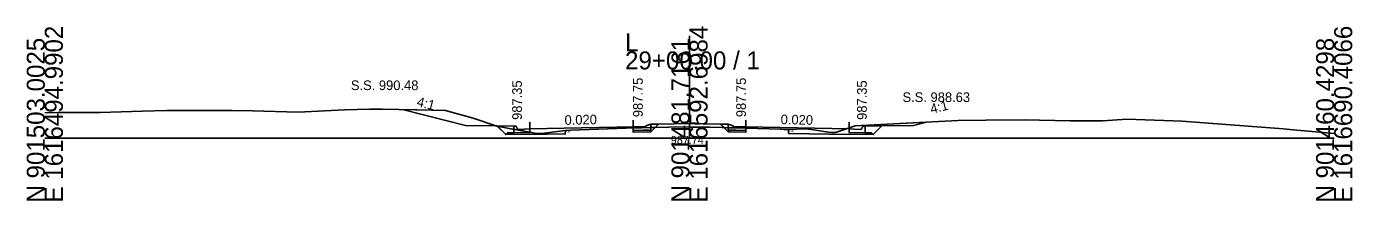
# Model space of a CAD drawing. Extents: x 1009 to 7438, y -1586 to 7964.
# Drawn here: x 2032.1 to 2237.7, y 6914 to 6941.1 of the extents above; entities that cross this region are included whole.
import ezdxf

# ---------------------------------------------------------------- set-up
doc = ezdxf.new("R2010")
doc.units = 0
for name, color, linetype in [('Default', 7, 'Continuous'), ('Exist Cross Section Cell', 7, 'Continuous'), ('Exist XS Center Line Elevation Label', 7, 'Continuous'), ('Exist XS Ground Line', 7, 'Continuous'), ('Prop XS Dump Level', 7, 'Continuous'), ('Prop XS Earthwork Shape', 7, 'Continuous'), ('Prop XS EOT Tick Mark', 7, 'Continuous'), ('Prop XS Finish Grade', 7, 'Continuous'), ('Prop XS Finish Grade CurbGutter', 7, 'Continuous'), ('Prop XS Finish Grade Earthwork', 7, 'Continuous'), ('Prop XS Finish Grade Pavement', 7, 'Continuous'), ('Prop XS Hydro Elevations', 7, 'Continuous'), ('Prop XS Pvmt Edge Slope', 7, 'Continuous'), ('Prop XS SE Text', 7, 'Continuous'), ('Prop XS Side Slope Text', 7, 'Continuous'), ('Prop XS SS Elevation Text', 7, 'Continuous'), ('Prop XS Subgrade CurbGutter', 7, 'Continuous'), ('Prop XS Subgrade Earthwork', 7, 'Continuous')]:
    doc.layers.add(name, color=color, linetype=linetype)

msp = doc.modelspace()

# ---------------------------------------------------------------- linework, layer by layer
at = {"layer": 'Default'}
msp.add_line((2134.89, 6923.73), (2134.89, 6939.67), dxfattribs=at)
at = {"layer": 'Exist Cross Section Cell'}
for p, q in [((2134.89, 6923.73), (2134.89, 6937.22)), ((2034.89, 6923.73), (2134.89, 6923.73)), ((2134.89, 6923.73), (2234.89, 6923.73))]:
    msp.add_line(p, q, dxfattribs=at)
at = {"layer": 'Exist XS Ground Line'}
for p, q in [((2034.89, 6927.67), (2036.92, 6927.71)), ((2036.92, 6927.71), (2043.5, 6927.71)), ((2043.5, 6927.71), (2050.01, 6927.95)), ((2050.01, 6927.95), (2053.74, 6928.02)), ((2053.74, 6928.02), (2063.1, 6928.05)), ((2063.1, 6928.05), (2063.97, 6928.04)), ((2063.97, 6928.04), (2067.13, 6928)), ((2067.13, 6928), (2074.21, 6927.78)), ((2074.21, 6927.78), (2081.35, 6928.13)), ((2081.35, 6928.13), (2085.24, 6928.23)), ((2085.24, 6928.23), (2087.26, 6928.23)), ((2087.26, 6928.23), (2094.9, 6928.11)), ((2094.9, 6928.11), (2097.04, 6928.05)), ((2097.04, 6928.05), (2101.36, 6926.85)), ((2101.36, 6926.85), (2104.84, 6925.65)), ((2104.84, 6925.65), (2107.18, 6925.2)), ((2125.05, 6925.27), (2127.5, 6925.36)), ((2127.5, 6925.36), (2131.68, 6925.46)), ((2131.68, 6925.46), (2132.73, 6925.49)), ((2132.73, 6925.49), (2134.89, 6925.47)), ((2134.89, 6925.47), (2137.15, 6925.44)), ((2137.15, 6925.44), (2138.04, 6925.43)), ((2138.04, 6925.43), (2139.94, 6925.38)), ((2139.94, 6925.38), (2149.07, 6925.12)), ((2157.53, 6924.63), (2160.6, 6925.66)), ((2160.6, 6925.66), (2161.55, 6925.71)), ((2161.55, 6925.71), (2176.56, 6926.49)), ((2176.56, 6926.49), (2180.87, 6926.52)), ((2180.87, 6926.52), (2186.79, 6926.59)), ((2186.79, 6926.59), (2193.95, 6926.45)), ((2193.95, 6926.45), (2197.03, 6926.43)), ((2197.03, 6926.43), (2199.01, 6926.42)), ((2199.01, 6926.42), (2202.73, 6926.69)), ((2202.73, 6926.69), (2211.32, 6926.36)), ((2211.32, 6926.36), (2224.95, 6925.35)), ((2224.95, 6925.35), (2227.03, 6925.21)), ((2107.18, 6925.2), (2111.17, 6924.47)), ((2111.17, 6924.47), (2111.92, 6924.47)), ((2111.92, 6924.47), (2113.57, 6924.65)), ((2113.57, 6924.65), (2115.63, 6924.92)), ((2115.63, 6924.92), (2116.43, 6924.99)), ((2116.43, 6924.99), (2125.05, 6925.27)), ((2149.07, 6925.12), (2149.56, 6925.1)), ((2149.56, 6925.1), (2150.27, 6925.06)), ((2150.27, 6925.06), (2152.79, 6925.21)), ((2152.79, 6925.21), (2153.8, 6925.09)), ((2153.8, 6925.09), (2156.78, 6924.63)), ((2156.78, 6924.63), (2157.13, 6924.63)), ((2157.13, 6924.63), (2157.53, 6924.63)), ((2227.03, 6925.21), (2228.54, 6925.05)), ((2228.54, 6925.05), (2229.73, 6924.94)), ((2229.73, 6924.94), (2234.89, 6924.47))]:
    msp.add_line(p, q, dxfattribs=at)
at = {"layer": 'Prop XS Dump Level'}
for p, q in [((2110.14, 6925.2), (2126.14, 6925.52)), ((2110.14, 6925.2), (2126.14, 6925.52)), ((2143.64, 6925.52), (2159.64, 6925.2)), ((2143.64, 6925.52), (2159.64, 6925.2))]:
    msp.add_line(p, q, dxfattribs=at)
at = {"layer": 'Prop XS Earthwork Shape'}
for points in [[(2100.14, 6925.73), (2090.37, 6928.18), (2094.9, 6928.11), (2097.04, 6928.05), (2101.36, 6926.85), (2104.84, 6925.65), (2104.95, 6925.63)], [(2105.05, 6925.63), (2104.95, 6925.63), (2105.08, 6925.61)], [(2106.64, 6924.55), (2106.39, 6924.29), (2105.08, 6925.61), (2107.18, 6925.2), (2107.64, 6925.11), (2107.64, 6924.57)], [(2127.64, 6924.97), (2128.64, 6924.99), (2128.89, 6924.99), (2128.89, 6925.39), (2127.5, 6925.36), (2126.14, 6925.31), (2126.14, 6924.94)], [(2128.89, 6924.99), (2128.89, 6925.39), (2129.56, 6925.41), (2128.89, 6924.74), (2128.64, 6924.99)], [(2134.89, 6926.02), (2139.67, 6925.92), (2139.72, 6925.92), (2140.27, 6925.37), (2139.94, 6925.38), (2138.04, 6925.43), (2137.15, 6925.44), (2134.89, 6925.47), (2132.73, 6925.49), (2131.68, 6925.46), (2129.56, 6925.41), (2130.07, 6925.92), (2130.12, 6925.92)], [(2141.14, 6924.99), (2140.9, 6924.74), (2140.27, 6925.37), (2140.89, 6925.35), (2140.89, 6924.99)], [(2143.64, 6924.94), (2142.14, 6924.97), (2141.14, 6924.99), (2140.89, 6924.99), (2140.89, 6925.35), (2143.64, 6925.27)], [(2161.52, 6925.11), (2161.61, 6925.21), (2161.68, 6925.46), (2161.77, 6925.55), (2161.89, 6925.58), (2162.14, 6925.58), (2164.73, 6925.63), (2169.64, 6925.73), (2171.65, 6926.24), (2161.55, 6925.71), (2160.6, 6925.66), (2157.53, 6924.63), (2157.13, 6924.63), (2156.78, 6924.63), (2153.8, 6925.09), (2152.79, 6925.21), (2150.27, 6925.06), (2150.27, 6924.47), (2159.64, 6924.28), (2159.64, 6924.37), (2163.39, 6924.29), (2163.14, 6924.55), (2162.14, 6924.57), (2159.64, 6924.62), (2159.64, 6925.2), (2161.39, 6925.09)], [(2162.14, 6924.57), (2162.14, 6925.58), (2161.89, 6925.58), (2161.77, 6925.55), (2161.68, 6925.46), (2161.61, 6925.21), (2161.52, 6925.11), (2161.39, 6925.09), (2159.64, 6925.2), (2159.64, 6924.62)], [(2162.14, 6924.57), (2162.14, 6925.58), (2164.73, 6925.63), (2163.39, 6924.29), (2163.14, 6924.55)], [(2110.14, 6924.28), (2110.14, 6924.37), (2106.39, 6924.29), (2106.64, 6924.55), (2107.64, 6924.57), (2110.14, 6924.62), (2110.14, 6924.66), (2111.17, 6924.47), (2111.92, 6924.47), (2113.57, 6924.65), (2115.64, 6924.92), (2115.63, 6924.39)], [(2110.14, 6924.62), (2107.64, 6924.57), (2107.64, 6925.11), (2110.14, 6924.66)], [(2127.64, 6924.97), (2128.64, 6924.99), (2128.89, 6924.74), (2126.14, 6924.69), (2126.14, 6924.94)], [(2141.14, 6924.99), (2140.9, 6924.74), (2143.64, 6924.69), (2143.64, 6924.94), (2142.14, 6924.97)]]:
    msp.add_lwpolyline(points, close=True, dxfattribs=at)
at = {"layer": 'Prop XS EOT Tick Mark'}
for p, q in [((2110.14, 6925.2), (2110.14, 6926.2)), ((2126.14, 6925.52), (2126.14, 6926.52)), ((2143.64, 6925.52), (2143.64, 6926.52)), ((2159.64, 6925.2), (2159.64, 6926.2))]:
    msp.add_line(p, q, dxfattribs=at)
at = {"layer": 'Prop XS Finish Grade'}
for p, q in [((2107.64, 6925.58), (2105.05, 6925.63)), ((2128.89, 6925.9), (2130.12, 6925.92)), ((2140.89, 6925.9), (2139.67, 6925.92)), ((2162.14, 6925.58), (2164.73, 6925.63))]:
    msp.add_line(p, q, dxfattribs=at)
at = {"layer": 'Prop XS Finish Grade CurbGutter'}
for p, q in [((2107.64, 6925.58), (2107.89, 6925.58)), ((2107.89, 6925.58), (2108.02, 6925.55)), ((2108.11, 6925.46), (2108.02, 6925.55)), ((2108.18, 6925.21), (2108.11, 6925.46)), ((2126.14, 6925.52), (2126.89, 6925.5)), ((2126.14, 6925.52), (2128.14, 6925.48)), ((2128.14, 6925.65), (2128.89, 6925.9)), ((2128.14, 6925.48), (2128.14, 6925.65)), ((2141.64, 6925.65), (2140.89, 6925.9)), ((2141.64, 6925.48), (2141.64, 6925.65)), ((2143.64, 6925.52), (2141.64, 6925.48)), ((2143.64, 6925.52), (2142.89, 6925.5)), ((2161.61, 6925.21), (2161.68, 6925.46)), ((2161.68, 6925.46), (2161.77, 6925.55)), ((2161.89, 6925.58), (2161.77, 6925.55)), ((2162.14, 6925.58), (2161.89, 6925.58)), ((2108.27, 6925.11), (2108.18, 6925.21)), ((2108.39, 6925.09), (2108.27, 6925.11)), ((2110.14, 6925.2), (2108.39, 6925.09)), ((2159.64, 6925.2), (2161.39, 6925.09)), ((2161.39, 6925.09), (2161.52, 6925.11)), ((2161.52, 6925.11), (2161.61, 6925.21))]:
    msp.add_line(p, q, dxfattribs=at)
at = {"layer": 'Prop XS Finish Grade Earthwork'}
for p, q in [((2100.14, 6925.73), (2090.37, 6928.18)), ((2105.05, 6925.63), (2100.14, 6925.73)), ((2130.12, 6925.92), (2134.89, 6926.02)), ((2134.89, 6926.02), (2139.67, 6925.92)), ((2164.73, 6925.63), (2169.64, 6925.73)), ((2169.64, 6925.73), (2171.65, 6926.24))]:
    msp.add_line(p, q, dxfattribs=at)
at = {"layer": 'Prop XS Finish Grade Pavement'}
for p, q in [((2110.14, 6925.2), (2126.14, 6925.52)), ((2143.64, 6925.52), (2159.64, 6925.2))]:
    msp.add_line(p, q, dxfattribs=at)
at = {"layer": 'Prop XS Pvmt Edge Slope'}
for p, q in [((2106.64, 6924.55), (2106.39, 6924.29)), ((2107.64, 6924.57), (2106.64, 6924.55)), ((2127.64, 6924.97), (2128.64, 6924.99)), ((2127.64, 6924.97), (2128.89, 6924.99)), ((2128.64, 6924.99), (2128.89, 6924.74)), ((2142.14, 6924.97), (2140.89, 6924.99)), ((2141.14, 6924.99), (2140.9, 6924.74)), ((2142.14, 6924.97), (2141.14, 6924.99)), ((2162.14, 6924.57), (2163.14, 6924.55)), ((2163.14, 6924.55), (2163.39, 6924.29))]:
    msp.add_line(p, q, dxfattribs=at)
at = {"layer": 'Prop XS Subgrade CurbGutter'}
for p, q in [((2107.64, 6924.57), (2107.64, 6925.58)), ((2126.14, 6925.52), (2126.14, 6924.94)), ((2128.89, 6924.99), (2128.89, 6925.9)), ((2140.89, 6924.99), (2140.89, 6925.9)), ((2143.64, 6925.52), (2143.64, 6924.94)), ((2162.14, 6924.57), (2162.14, 6925.58)), ((2110.14, 6924.62), (2107.64, 6924.57)), ((2110.14, 6925.2), (2110.14, 6924.62)), ((2126.14, 6924.94), (2127.64, 6924.97)), ((2143.64, 6924.94), (2142.14, 6924.97)), ((2159.64, 6925.2), (2159.64, 6924.62)), ((2159.64, 6924.62), (2162.14, 6924.57))]:
    msp.add_line(p, q, dxfattribs=at)
at = {"layer": 'Prop XS Subgrade Earthwork'}
for p, q in [((2106.39, 6924.29), (2105.05, 6925.63)), ((2126.14, 6924.6), (2126.14, 6925.31)), ((2128.89, 6924.74), (2130.07, 6925.92)), ((2140.9, 6924.74), (2139.72, 6925.92)), ((2163.39, 6924.29), (2164.73, 6925.63)), ((2110.14, 6924.37), (2106.39, 6924.29)), ((2115.63, 6924.39), (2110.14, 6924.28)), ((2110.14, 6924.28), (2110.14, 6924.37)), ((2115.63, 6924.39), (2115.64, 6924.92)), ((2126.14, 6924.69), (2128.89, 6924.74)), ((2126.14, 6924.6), (2126.14, 6924.69)), ((2143.64, 6924.69), (2140.9, 6924.74)), ((2143.64, 6924.6), (2143.64, 6925.27)), ((2143.64, 6924.6), (2143.64, 6924.69)), ((2150.27, 6924.47), (2150.27, 6925.06)), ((2150.27, 6924.47), (2159.64, 6924.28)), ((2159.64, 6924.28), (2159.64, 6924.37)), ((2159.64, 6924.37), (2163.39, 6924.29))]:
    msp.add_line(p, q, dxfattribs=at)

# ---------------------------------------------------------------- texts
at = {"layer": 'Exist Cross Section Cell'}
for s, p in [('E 1616494.9902', (2037.69, 6913.73)), ('E 1616592.6984', (2137.69, 6913.73)), ('E 1616690.4066', (2237.69, 6913.73)), ('N 901503.0025', (2034.89, 6913.73)), ('N 901481.7161', (2134.89, 6913.73)), ('N 901460.4298', (2234.89, 6913.73))]:
    msp.add_text(s, height=2.8, rotation=90, dxfattribs=at).set_placement(p)
for s, p in [('L', (2124.89, 6937.22)), ('29+00.00 / 1', (2124.89, 6934.42))]:
    msp.add_text(s, height=2.8, dxfattribs=at).set_placement(p)
at = {"layer": 'Exist XS Center Line Elevation Label'}
msp.add_text('987.74', height=1.25, dxfattribs=at).set_placement((2131.99, 6922.84))
at = {"layer": 'Prop XS Dump Level'}
for p in [(2115.63, 6924.62), (2115.63, 6924.62), (2150.27, 6924.76), (2150.27, 6924.76)]:
    msp.add_text('Eop', height=0.3, dxfattribs=at).set_placement(p)
at = {"layer": 'Prop XS Hydro Elevations'}
for s, p in [('987.35', (2108.89, 6926.58)), ('987.75', (2127.64, 6927)), ('987.75', (2143.64, 6927)), ('987.35', (2162.39, 6926.58))]:
    msp.add_text(s, height=1.5, rotation=90, dxfattribs=at).set_placement(p)
at = {"layer": 'Prop XS SE Text'}
for rotation, p in [(1.1458, (2115.52, 6925.8)), (358.8542, (2149.02, 6925.91))]:
    msp.add_text('0.020', height=1.5, rotation=rotation, dxfattribs=at).set_placement(p)
at = {"layer": 'Prop XS Side Slope Text'}
for rotation, p in [(345.9638, (2092.49, 6928.74)), (14.0362, (2172.44, 6927.52))]:
    msp.add_text('4:1', height=1.5, rotation=rotation, dxfattribs=at).set_placement(p)
at = {"layer": 'Prop XS SS Elevation Text'}
for s, p in [('S.S. 990.48', (2082.36, 6931.21)), ('S.S. 988.63', (2167.93, 6929.36))]:
    msp.add_text(s, height=1.5, dxfattribs=at).set_placement(p)

doc.saveas('drawing.dxf')
